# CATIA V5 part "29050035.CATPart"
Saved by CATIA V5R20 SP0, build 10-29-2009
Part number: 29050035
Definition: NONE
Nomenclature: 29050035
Source: Unknown
Description: 29050035
Bounding box of the stored display mesh (mm): x -17.5 to 44.548, y -39 to 73.548, z -29 to 29
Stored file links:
  C:\Users\Utente\Desktop\IO LAVORO\3D X SITO CF\X SITO\PLASTICA\RF1\29050035.CATPart
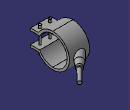
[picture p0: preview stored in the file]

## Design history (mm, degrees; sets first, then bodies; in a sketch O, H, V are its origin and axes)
Body1 "29050035" (main body)
  Solid1: solid without history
